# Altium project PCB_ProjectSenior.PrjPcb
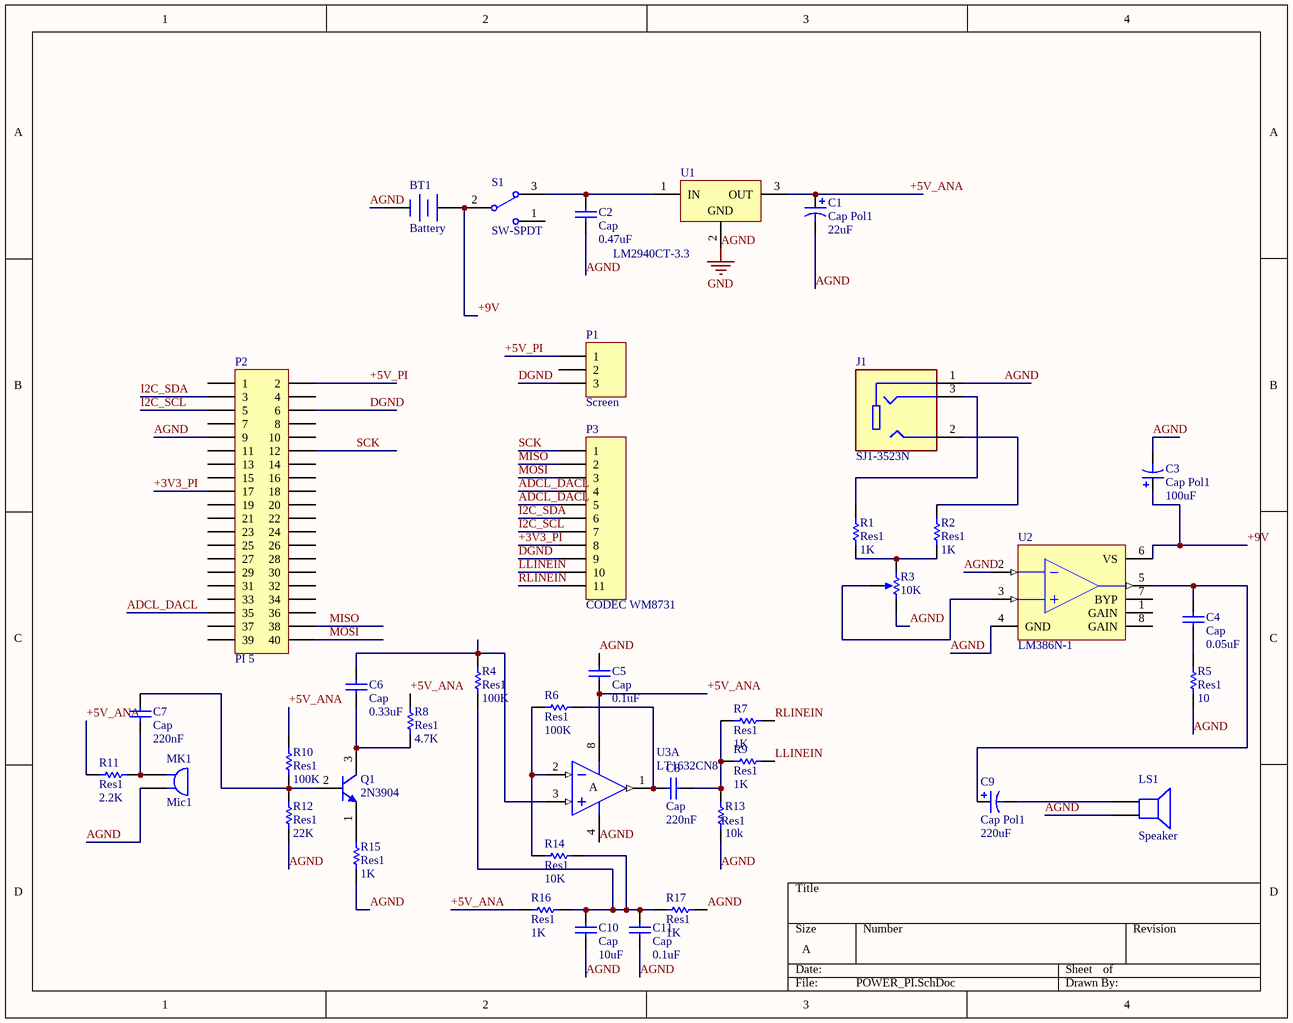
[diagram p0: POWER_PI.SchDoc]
2 sheets, 40 parts. Net scope: global (net labels, ports and power ports of the same name join across sheets).
Board file: Senior_Desing_PCB_Rev1.PcbDoc
Sheets:
  POWER_PI.SchDoc
  CODEC_INTERFACE.SchDoc

## Sheet POWER_PI.SchDoc
size A; SheetNumber: 1; SheetTotal: 2

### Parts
BT1  Battery  [BAT-2]
C1  Cap Pol1  value 22uF  [RB7.6-15]
C2  Cap  value 0.47uF  [RAD-0.3]
C3  Cap Pol1  value 100uF  [RB7.6-15]
C4  Cap  value 0.05uF  [RAD-0.3]
C5  Cap  value 0.1uF  [RAD-0.3]
C6  Cap  value 0.33uF  [RAD-0.3]
C7  Cap  value 220nF  [RAD-0.3]
C8  Cap  value 220nF  [RAD-0.3]
C9  Cap Pol1  value 220uF  [RB7.6-15]
C10  Cap  value 10uF  [RAD-0.3]
C11  Cap  value 0.1uF  [RAD-0.3]
J1  SJ1-3523N  [CUI_SJ1-3523N]
LS1  Speaker  [PIN2]
MK1  Mic1  [PIN2]
P1  Screen  [HDR1X3]
P2  PI 5  [HDR2X20]
P3  CODEC WM8731  [HDR1X11]
Q1  2N3904  [TO92C]
R1  Res1  value 1K  [AXIAL-0.3]
R2  Res1  value 1K  [AXIAL-0.3]
R3  value 10K  [POT OFFSET 200]  (hidden comment: RPot_3)
R4  Res1  value 100K  [AXIAL-0.3]
R5  Res1  value 10  [AXIAL-0.3]
R6  Res1  value 100K  [AXIAL-0.3]
R7  Res1  value 1K  [AXIAL-0.3]
R8  Res1  value 4.7K  [AXIAL-0.3]
R9  Res1  value 1K  [AXIAL-0.3]
R10  Res1  value 100K  [AXIAL-0.3]
R11  Res1  value 2.2K  [AXIAL-0.3]
R12  Res1  value 22K  [AXIAL-0.3]
R13  Res1  value 10k  [AXIAL-0.3]
R14  Res1  value 10K  [AXIAL-0.3]
R15  Res1  value 1K  [AXIAL-0.3]
R16  Res1  value 1K  [AXIAL-0.3]
R17  Res1  value 1K  [AXIAL-0.3]
S1  SW-SPDT  [SW DPST jameco]
U1  LM2940CT-3.3  [T03B]
U2  LM386N-1  [DIP-8]
U3  LT1632CN8  [DIP-8]  (part A of 2)

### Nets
AGND: BT1.2(-) C1.2 C2.1 C3.2 C5.2 C10.1 C11.1 J1.1 LS1.2 MK1.2 P2.9 R3.3(BOT) R5.1 R12.1 R13.1 R15.1 R17.2 U1.2(GND) U2.2(IN-) U2.4(GND) U3.4(V-)  [also labelled GND]
+3V3_PI: P2.17 P3.8
+5V_ANA: C1.1 C5.1 R8.2 R10.2 R11.1 R16.1 U1.3(OUT) U3.8(V+)
+5V_PI: P1.1 P2.2
+9V: BT1.1(+) C3.1 S1.2 U2.6(VS)
ADCL_DACL: P2.35 P3.4 P3.5
DGND: P1.3 P2.6 P3.9
I2C_SCL: P2.5 P3.7
I2C_SDA: P2.3 P3.6
LLINEIN: P3.10 R9.2
MISO: P2.38 P3.2
MOSI: P2.40 P3.3
RLINEIN: P3.11 R7.2
SCK: P2.12 P3.1
NetC2_2: C2.2 S1.3 U1.1(IN)
NetC4_1: C4.1 R5.2
NetC4_2: C4.2 C9.1 U2.5(OUT)
NetC6_1: C6.1 Q1.3(C) R8.1
NetC6_2: C6.2 R4.2 U3.3(IN+)
NetC7_1: C7.1 MK1.1 R11.2
NetC7_2: C7.2 Q1.2(B) R10.1 R12.2
NetC8_1: C8.1 R6.2 U3.1(OUT)
NetC8_2: C8.2 R7.1 R9.1 R13.2
NetC9_2: C9.2 LS1.1
NetC10_2: C10.2 C11.2 R4.1 R14.2 R16.2 R17.1
NetJ1_2: J1.2 R2.2
NetJ1_3: J1.3 R1.2
NetQ1_1: Q1.1(E) R15.2
NetR1_1: R1.1 R2.1 R3.1(TOP)
NetR3_2: R3.2(TAP) U2.3(IN+)
NetR6_1: R6.1 R14.1 U3.2(IN-)

Not connected (* = marked no-connect by the designer): P1 2; P2 1 4 7 8 10 11 13 14 15 16 18 19 20 21 22 23 24 25 26 27 28 29 30 31 32 33 34 36 37 39; S1 1; U2 1(GAIN) 7(BYP) 8(GAIN)

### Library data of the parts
BT1 = Battery: Multicell Battery
C1 C3 C9 = Cap Pol1: Polarized Capacitor (Radial)
C2 C4-C8 C10 C11 = Cap: Capacitor
J1 = SJ1-3523N: 3.5 mm, Stereo, Right Angle, Through Hole, 3 Conductors, 0 Internal Switches, Audio Jack Connector; MF: Same Sky
LS1 = Speaker: Loudspeaker
MK1 = Mic1: Microphone
P1 = Header 3: Header, 3-Pin
P2 = Header 20X2: Header, 20-Pin, Dual row
P3 = Header 11: Header, 11-Pin
Q1 = 2N3904: NPN General Purpose Amplifier
R1 R2 R4-R17 = Res1: Resistor
R3 = RPot: Potentiometer; Sim Note: Enter the Resistance value and the set point into parameter fields.; Set Position: 0.5
S1 = SW-SPDT: SPDT Subminiature Toggle Switch, Right Angle Mounting, Vertical Actuation
U1 = LM2940CT-5.0: 1A Low Dropout Regulator, 3-pin TO-220; Manufacturer: National Semiconductor; PackageTopMarking: NSUZXYTTE#*LM2940CT*-5.0 P+; PowerWise: N; CompType: LDO IC; High-Reliability: Y
U2 = LM386N-1: Low-Voltage Audio Power Amplifier
U3 = LT1632CN8: 45MHz, 45V/µs, Dual Rail-to-Rail Input and Output Precision Operational Amplifier; Note: 1455

## Sheet CODEC_INTERFACE.SchDoc
size A; SheetNumber: 2; SheetTotal: 2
